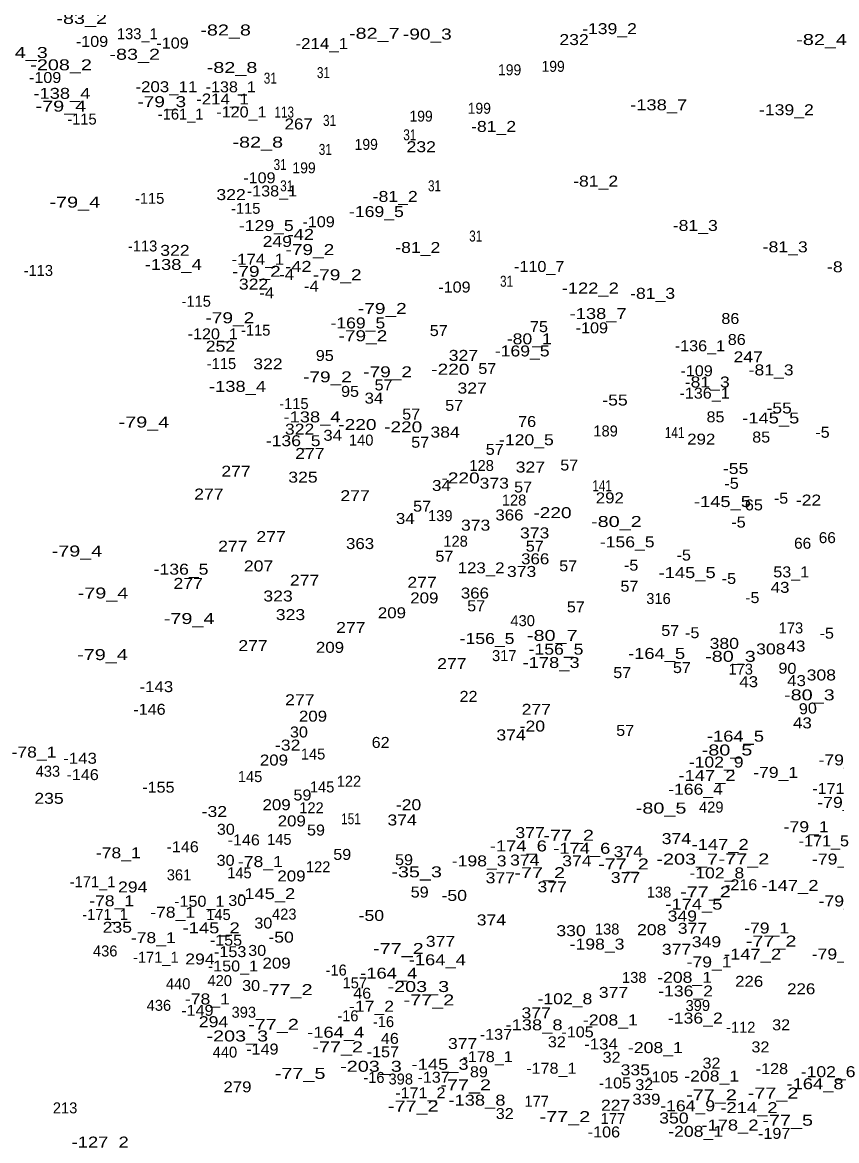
# Model space of a CAD drawing. Extents: x -658110 to -655750, y -1000429 to -997657.
# Drawn here: x -657300 to -657003, y -998729.8 to -998321.9 of the extents above; entities that cross this region are included whole.
import ezdxf
from ezdxf.enums import TextEntityAlignment as Align

# ---------------------------------------------------------------- set-up
doc = ezdxf.new("R2010")
doc.units = 0
doc.header["$LTSCALE"] = 1.6
doc.layers.add('24', color=7, linetype='Continuous')

msp = doc.modelspace()

# ---------------------------------------------------------------- texts
at = {"layer": '24'}
for s, width, p in [('-83_2', 1.35, (-657278.34, -998322.43)), ('-139_2', 1.2, (-657085.831, -998326.15)), ('-82_8', 1.35, (-657225.85, -998326.64)), ('-82_7', 1.35, (-657171.62, -998327.85)), ('-90_3', 1.3, (-657152.27, -998328.13)), ('232', 1.2, (-657098.76, -998330.13)), ('-82_4', 1.35, (-657008.49, -998330.12)), ('-109', 1.1, (-657274.58, -998330.81)), ('-109', 1.1, (-657245.21, -998331.39)), ('-214_1', 1.15, (-657190.77, -998331.59)), ('-84_3', 1.35, (-657299.94, -998334.85)), ('-83_2', 1.35, (-657259, -998335.49)), ('-208_2', 1.35, (-657285.86, -998339.34)), ('-82_8', 1.35, (-657223.52, -998340.31)), ('31', 0.8, (-657190.169, -998342.18)), ('199', 0.95, (-657122.26, -998341.15)), ('199', 0.95, (-657106.4, -998339.9)), ('-109', 1.1, (-657291.68, -998343.97)), ('31', 0.8, (-657209.559, -998344.21)), ('-138_4', 1.25, (-657285.559, -998349.75)), ('-203_11', 1.15, (-657247.45, -998347.33)), ('-138_1', 1.1, (-657223.98, -998347.38)), ('-79_4', 1.35, (-657285.931, -998354.42)), ('-79_3', 1.3, (-657249.15, -998352.78)), ('-214_1', 1.15, (-657227.01, -998351.81)), ('-138_7', 1.25, (-657067.9, -998353.93)), ('-120_1', 1.1, (-657220.08, -998356.53)), ('113', 0.8, (-657204.47, -998356.6)), ('199', 0.95, (-657154.56, -998358.07)), ('199', 0.95, (-657133.32, -998355.19)), ('-139_2', 1.2, (-657021.321, -998355.73)), ('267', 1.15, (-657199.19, -998360.91)), ('31', 0.8, (-657187.939, -998359.63)), ('-81_2', 1.2, (-657128.12, -998361.81)), ('31', 0.8, (-657158.669, -998364.87)), ('-82_8', 1.35, (-657214.12, -998367.56)), ('31', 0.8, (-657189.49, -998370.2)), ('199', 0.95, (-657174.56, -998368.36)), ('232', 1.2, (-657154.5, -998369.22)), ('31', 0.8, (-657205.97, -998375.72)), ('199', 0.95, (-657197.24, -998376.92)), ('-109', 1.1, (-657213.53, -998380.56)), ('31', 0.8, (-657203.559, -998383.49)), ('31', 0.8, (-657149.65, -998383.48)), ('-81_2', 1.2, (-657090.9, -998381.77)), ('322', 1.2, (-657223.85, -998386.69)), ('-138_1', 1.1, (-657208.949, -998385.37)), ('-81_2', 1.2, (-657164, -998387.36)), ('-79_4', 1.35, (-657280.851, -998389.44)), ('-169_5', 1.2, (-657170.84, -998392.88)), ('-129_5', 1.2, (-657211.02, -998397.98)), ('-109', 1.1, (-657191.93, -998396.6)), ('-81_3', 1.2, (-657054.559, -998397.95)), ('249', 1.2, (-657206.99, -998403.78)), ('-42', 1.25, (-657198.43, -998401.21)), ('31', 0.8, (-657134.63, -998401.81)), ('322', 1.2, (-657244.34, -998407.03)), ('-79_2', 1.3, (-657195.111, -998406.75)), ('-81_2', 1.2, (-657155.76, -998405.98)), ('-81_3', 1.2, (-657021.75, -998405.75)), ('-138_4', 1.25, (-657244.939, -998412.19)), ('-174_1', 1.15, (-657214.13, -998410.29)), ('-79_2', 1.3, (-657214.63, -998414.69)), ('-4', 1.15, (-657203.59, -998415.79)), ('-42', 1.25, (-657199.32, -998412.89)), ('-79_2', 1.3, (-657185.15, -998415.94)), ('-110_7', 1.1, (-657111.471, -998412.91)), ('-81_3', 1.2, (-656998.29, -998413.02)), ('322', 1.2, (-657215.65, -998419.33)), ('-4', 1.15, (-657194.58, -998420.06)), ('31', 0.8, (-657123.38, -998418.3)), ('-4', 1.15, (-657210.86, -998422.48)), ('-109', 1.1, (-657142.39, -998420.42)), ('-122_2', 1.25, (-657092.86, -998420.79)), ('-81_3', 1.2, (-657070.12, -998422.72)), ('-79_2', 1.3, (-657168.701, -998428.23)), ('-79_2', 1.3, (-657224.301, -998431.62)), ('-138_7', 1.25, (-657089.98, -998430.09)), ('86', 1.1, (-657041.76, -998431.9)), ('-169_5', 1.2, (-657177.62, -998433.52)), ('57', 1.1, (-657148.12, -998436.3)), ('75', 1.1, (-657111.56, -998434.86)), ('-109', 1.1, (-657092.27, -998435.3)), ('-120_1', 1.1, (-657230.54, -998437.49)), ('-79_2', 1.3, (-657175.77, -998438.19)), ('-80_1', 1.2, (-657115.09, -998439.31)), ('86', 1.1, (-657039.43, -998439.56)), ('252', 1.2, (-657227.73, -998441.98)), ('-169_5', 1.2, (-657117.67, -998443.73)), ('-136_1', 1.1, (-657052.861, -998441.84)), ('322', 1.2, (-657210.419, -998448.44)), ('95', 1.1, (-657189.68, -998445.39)), ('327', 1.2, (-657139.12, -998445.35)), ('247', 1.2, (-657035.25, -998445.89)), ('-79_2', 1.3, (-657166.77, -998451.35)), ('-220', 1.3, (-657143.89, -998450.4)), ('57', 1.1, (-657130.41, -998450.14)), ('-109', 1.1, (-657054.06, -998450.97)), ('-81_3', 1.2, (-657026.89, -998450.65)), ('-138_4', 1.25, (-657221.51, -998456.65)), ('-79_2', 1.3, (-657188.721, -998453.18)), ('57', 1.1, (-657168.24, -998456.13)), ('-81_3', 1.2, (-657050.189, -998455.06)), ('95', 1.1, (-657180.47, -998458.48)), ('34', 1.15, (-657171.75, -998460.94)), ('327', 1.2, (-657135.93, -998457.27)), ('-136_1', 1.1, (-657051.16, -998459.13)), ('57', 1.1, (-657142.5, -998463.58)), ('-55', 1.2, (-657083.83, -998461.65)), ('-55', 1.2, (-657023.96, -998464.54)), ('-138_4', 1.25, (-657194.34, -998467.79)), ('57', 1.1, (-657158.16, -998466.78)), ('85', 1.1, (-657047.179, -998467.78)), ('-145_5', 1.25, (-657027.03, -998468.19)), ('-79_4', 1.35, (-657255.64, -998469.67)), ('322', 1.2, (-657198.87, -998472.28)), ('-220', 1.3, (-657177.79, -998470.57)), ('-220', 1.3, (-657161.08, -998471.43)), ('384', 1.2, (-657145.799, -998473.34)), ('76', 1.1, (-657115.88, -998469.47)), ('-136_5', 1.2, (-657201.211, -998476.49)), ('34', 1.15, (-657186.799, -998474.5)), ('57', 1.1, (-657154.88, -998477.03)), ('-120_5', 1.2, (-657116.14, -998476.14)), ('141', 0.8, (-657062.079, -998473.52)), ('292', 1.15, (-657052.37, -998475.91)), ('85', 1.1, (-657030.51, -998475.15)), ('-5', 1.1, (-657008.16, -998473.4)), ('277', 1.2, (-657195.111, -998481.11)), ('57', 1.1, (-657127.7, -998479.64)), ('57', 1.1, (-657100.52, -998485.35)), ('277', 1.2, (-657222.051, -998487.6)), ('327', 1.2, (-657114.69, -998486.08)), ('-55', 1.2, (-657039.84, -998486.62)), ('325', 1.2, (-657197.64, -998489.77)), ('34', 1.15, (-657147.13, -998492.82)), ('-220', 1.3, (-657140.15, -998490.06)), ('373', 1.2, (-657127.87, -998491.98)), ('57', 1.1, (-657117.35, -998493.38)), ('141', 0.8, (-657088.54, -998492.91)), ('-5', 1.1, (-657041.31, -998492.02)), ('277', 1.2, (-657231.941, -998495.94)), ('277', 1.2, (-657178.63, -998496.53)), ('292', 1.15, (-657085.72, -998497.34)), ('-5', 1.1, (-657023.28, -998497.45)), ('57', 1.1, (-657154.19, -998500.35)), ('-145_5', 1.25, (-657044.65, -998498.68)), ('65', 1.1, (-657033.17, -998499.9)), ('-22', 1.2, (-657013.25, -998498.13)), ('34', 1.15, (-657160.319, -998504.86)), ('366', 1.15, (-657122.33, -998503.56)), ('-220', 1.3, (-657106.63, -998502.73)), ('-80_2', 1.35, (-657083.329, -998505.97)), ('373', 1.2, (-657134.66, -998507.3)), ('373', 1.2, (-657113.14, -998510.12)), ('-5', 1.1, (-657038.79, -998506.18)), ('277', 1.2, (-657209.26, -998511.46)), ('363', 1.15, (-657176.81, -998514.01)), ('-156_5', 1.2, (-657079.38, -998513.39)), ('66', 1.05, (-657015.39, -998513.89)), ('66', 1.05, (-657006.4, -998511.85)), ('-79_4', 1.35, (-657280.071, -998516.73)), ('277', 1.2, (-657223.221, -998514.95)), ('57', 1.1, (-657113.1, -998514.94)), ('-5', 1.1, (-657058.76, -998518.2)), ('207', 1.2, (-657213.82, -998522.18)), ('57', 1.1, (-657146.07, -998518.63)), ('366', 1.15, (-657112.93, -998519.56)), ('57', 1.1, (-657100.9, -998522.12)), ('-5', 1.1, (-657077.95, -998521.89)), ('-136_5', 1.2, (-657242.111, -998523.36)), ('123_2', 1.15, (-657132.67, -998522.86)), ('373', 1.2, (-657117.89, -998524.18)), ('-145_5', 1.25, (-657057.52, -998524.61)), ('53_1', 1.1, (-657019.55, -998524.35)), ('277', 1.2, (-657239.5, -998528.53)), ('277', 1.2, (-657197.041, -998527.36)), ('277', 1.2, (-657154.201, -998528.14)), ('57', 1.1, (-657078.57, -998529.56)), ('-5', 1.1, (-657042.28, -998526.74)), ('43', 1.15, (-657023.63, -998529.98)), ('-79_4', 1.35, (-657270.571, -998532.05)), ('323', 1.2, (-657206.73, -998533.14)), ('209', 1.15, (-657153.37, -998533.83)), ('366', 1.15, (-657134.93, -998532.06)), ('-5', 1.1, (-657033.75, -998533.72)), ('57', 1.1, (-657134.46, -998536.7)), ('57', 1.1, (-657098.12, -998537.11)), ('-79_4', 1.35, (-657239.16, -998541.36)), ('323', 1.2, (-657202.179, -998539.93)), ('209', 1.15, (-657165.191, -998539.26)), ('277', 1.2, (-657180.181, -998544.62)), ('57', 1.1, (-657063.68, -998545.71)), ('-5', 1.1, (-657055.66, -998546.52)), ('-5', 1.1, (-657006.61, -998546.71)), ('-156_5', 1.2, (-657130.49, -998548.64)), ('-80_7', 1.35, (-657106.71, -998547.53)), ('380', 1.2, (-657043.97, -998550.42)), ('-79_4', 1.35, (-657270.76, -998554.52)), ('277', 1.2, (-657215.851, -998551.22)), ('209', 1.15, (-657187.78, -998551.87)), ('-156_5', 1.2, (-657105.341, -998552.54)), ('-164_5', 1.25, (-657068.65, -998554.09)), ('308', 1.2, (-657027, -998552.44)), ('43', 1.15, (-657017.819, -998551.4)), ('277', 1.2, (-657143.341, -998557.81)), ('-178_3', 1.25, (-657107.13, -998557.41)), ('-80_3', 1.35, (-657041.72, -998555.15)), ('57', 1.1, (-657081.19, -998561.09)), ('57', 1.1, (-657059.43, -998559.25)), ('308', 1.2, (-657008.579, -998561.94)), ('-143', 1.15, (-657251.11, -998566.21)), ('43', 1.15, (-657035.069, -998564.4)), ('43', 1.15, (-657017.62, -998564.01)), ('277', 1.2, (-657198.78, -998570.99)), ('22', 1.1, (-657137.25, -998569.75)), ('-80_3', 1.35, (-657012.939, -998569.21)), ('-146', 1.1, (-657253.62, -998574.48)), ('277', 1.2, (-657112.52, -998574.48)), ('209', 1.15, (-657193.981, -998576.98)), ('43', 1.15, (-657015.48, -998579.43)), ('30', 1.1, (-657199.11, -998582.75)), ('-20', 1.2, (-657113.97, -998580.59)), ('57', 1.1, (-657080.12, -998582.18)), ('-32', 1.2, (-657203.21, -998587.53)), ('62', 1.1, (-657169.3, -998586.56)), ('374', 1.2, (-657121.73, -998583.82)), ('-164_5', 1.25, (-657039.9, -998584.28)), ('-78_1', 1.2, (-657295.75, -998590.08)), ('-80_5', 1.35, (-657042.98, -998589.31)), ('-143', 1.15, (-657278.95, -998592.34)), ('209', 1.15, (-657208.221, -998592.99)), ('-102_9', 1.2, (-657046.931, -998593.72)), ('-79_1', 1.2, (-657001.4, -998592.93)), ('-146', 1.1, (-657278, -998598.3)), ('-147_2', 1.25, (-657050.27, -998598.61)), ('-79_1', 1.2, (-657025.23, -998597.48)), ('-155', 1.1, (-657250.37, -998602.89)), ('-166_4', 1.2, (-657054.459, -998603.63)), ('-171_5', 1.1, (-657002.721, -998603.37)), ('235', 1.2, (-657290.26, -998606.95)), ('59', 1.1, (-657197.83, -998605.74)), ('-32', 1.2, (-657229.96, -998611.77)), ('209', 1.15, (-657207.25, -998609.28)), ('-20', 1.2, (-657159.14, -998609.29)), ('-80_5', 1.35, (-657067.02, -998610.52)), ('-79_1', 1.2, (-657001.83, -998608.42)), ('209', 1.15, (-657201.731, -998615.19)), ('151', 0.8, (-657180.13, -998614.41)), ('374', 1.2, (-657161.47, -998614.85)), ('30', 1.1, (-657225.77, -998618.24)), ('59', 1.1, (-657192.89, -998618.51)), ('377', 1.2, (-657114.801, -998619.46)), ('-79_1', 1.2, (-657014.11, -998617.31)), ('-146', 1.1, (-657219.24, -998622.12)), ('-174_6', 1.25, (-657119.081, -998624.32)), ('-77_2', 1.35, (-657100.74, -998620.44)), ('374', 1.2, (-657061.43, -998621.64)), ('-147_2', 1.25, (-657045.47, -998623.77)), ('-171_5', 1.1, (-657007.66, -998622.48)), ('-78_1', 1.2, (-657264.99, -998626.84)), ('-146', 1.1, (-657241.52, -998624.62)), ('59', 1.1, (-657183.31, -998627.41)), ('-174_6', 1.25, (-657095.941, -998625.18)), ('374', 1.2, (-657078.97, -998626.4)), ('30', 1.1, (-657225.86, -998629.58)), ('-78_1', 1.2, (-657213.17, -998630.03)), ('59', 1.1, (-657160.78, -998629.35)), ('-198_3', 1.2, (-657133.38, -998629.78)), ('374', 1.2, (-657116.74, -998629.47)), ('374', 1.2, (-657097.73, -998629.75)), ('-77_2', 1.35, (-657080.731, -998630.9)), ('-203_7', 1.35, (-657057.49, -998629.12)), ('-77_2', 1.35, (-657036.821, -998629.05)), ('-79_1', 1.2, (-657003.77, -998629.11)), ('209', 1.15, (-657201.831, -998635.27)), ('-35_3', 1.35, (-657156.179, -998633.78)), ('377', 1.2, (-657125.66, -998635.94)), ('-77_2', 1.35, (-657111.28, -998634.07)), ('377', 1.2, (-657080, -998635.85)), ('-102_8', 1.2, (-657046.699, -998634.16)), ('294', 1.2, (-657259.73, -998639.29)), ('377', 1.2, (-657106.75, -998639.24)), ('-216', 1.1, (-657037.83, -998638.48)), ('-147_2', 1.25, (-657020.03, -998638.74)), ('-78_1', 1.2, (-657267.41, -998644.35)), ('-150_1', 1.1, (-657235.46, -998644.51)), ('30', 1.1, (-657221.6, -998644.22)), ('-145_2', 1.25, (-657210.87, -998641.73)), ('59', 1.1, (-657155.07, -998641.15)), ('-50', 1.2, (-657142.46, -998642.38)), ('-77_2', 1.35, (-657050.821, -998641.08)), ('-79_1', 1.2, (-657001.35, -998644.4)), ('-78_1', 1.2, (-657245.17, -998648.51)), ('-174_5', 1.25, (-657055.06, -998645.56)), ('30', 1.1, (-657212.1, -998652.46)), ('-50', 1.2, (-657172.69, -998649.69)), ('374', 1.2, (-657128.9, -998651.31)), ('349', 1.2, (-657059.28, -998649.88)), ('235', 1.2, (-657265.35, -998653.98)), ('-145_2', 1.25, (-657231.12, -998654.21)), ('330', 1.2, (-657099.87, -998655.23)), ('208', 1.2, (-657070.449, -998654.88)), ('377', 1.2, (-657055.571, -998654.37)), ('-79_1', 1.2, (-657028.53, -998654.26)), ('-78_1', 1.2, (-657252.23, -998657.79)), ('-155', 1.1, (-657225.711, -998658.7)), ('-50', 1.2, (-657205.61, -998657.59)), ('377', 1.2, (-657147.471, -998659.12)), ('-198_3', 1.2, (-657090.38, -998660.13)), ('349', 1.2, (-657050.47, -998659.28)), ('-77_2', 1.35, (-657026.87, -998659.03)), ('-153', 1.1, (-657224.181, -998662.89)), ('30', 1.1, (-657214.329, -998662.45)), ('-77_2', 1.35, (-657162.831, -998661.75)), ('377', 1.2, (-657061.39, -998662.03)), ('-147_2', 1.25, (-657033.66, -998663.8)), ('-79_1', 1.2, (-657003.87, -998663.75)), ('294', 1.2, (-657235.21, -998665.57)), ('-150_1', 1.1, (-657223.17, -998668.13)), ('209', 1.15, (-657207.26, -998667.08)), ('-164_4', 1.25, (-657148.64, -998665.86)), ('-79_1', 1.2, (-657049.51, -998666.64)), ('-164_4', 1.25, (-657166.35, -998670.74)), ('-208_1', 1.2, (-657058.449, -998672.26)), ('30', 1.1, (-657216.559, -998675.25)), ('-77_2', 1.35, (-657203.351, -998676.74)), ('-203_3', 1.35, (-657155.569, -998675.62)), ('-136_2', 1.2, (-657058.081, -998677.24)), ('226', 1.15, (-657034.9, -998673.72)), ('226', 1.15, (-657015.91, -998676.44)), ('-78_1', 1.2, (-657232.5, -998680.15)), ('46', 1.1, (-657176.03, -998678.05)), ('-77_2', 1.35, (-657151.711, -998680.51)), ('-102_8', 1.2, (-657102.1, -998680.07)), ('377', 1.2, (-657084.37, -998677.75)), ('-149', 1.1, (-657236.15, -998684.3)), ('-17_2', 1.2, (-657172.63, -998682.8)), ('377', 1.2, (-657112.571, -998685.21)), ('294', 1.2, (-657230.26, -998688.45)), ('-77_2', 1.35, (-657208.38, -998689.41)), ('-138_8', 1.25, (-657113.36, -998689.6)), ('-208_1', 1.2, (-657085.52, -998687.81)), ('-136_2', 1.2, (-657054.53, -998687.13)), ('32', 1.1, (-657023.23, -998689.59)), ('-203_3', 1.35, (-657221.59, -998693.65)), ('-164_4', 1.25, (-657185.7, -998692.3)), ('-137', 1.1, (-657127.25, -998693.05)), ('-105', 1.1, (-657097.49, -998692.17)), ('-77_2', 1.35, (-657184.99, -998697.64)), ('46', 1.1, (-657165.95, -998694.54)), ('377', 1.2, (-657139.41, -998696.41)), ('32', 1.1, (-657105.049, -998695.8)), ('-134', 1.15, (-657088.94, -998696.57)), ('32', 1.1, (-657030.799, -998697.64)), ('-149', 1.1, (-657212.441, -998698.42)), ('-157', 1.1, (-657168.5, -998699.43)), ('-178_1', 1.1, (-657130.291, -998701.2)), ('32', 1.1, (-657085.079, -998701.42)), ('-208_1', 1.2, (-657069.1, -998697.9)), ('-203_3', 1.35, (-657172.829, -998704.71)), ('-145_3', 1.25, (-657147.63, -998703.98)), ('-178_1', 1.1, (-657107.051, -998705.42)), ('32', 1.1, (-657048.63, -998703.55)), ('-128', 1.1, (-657026.611, -998705.58)), ('-77_5', 1.35, (-657198.66, -998707.31)), ('-137', 1.1, (-657149.99, -998708.71)), ('89', 1.1, (-657133.47, -998706.72)), ('335', 1.2, (-657076.429, -998706.01)), ('-105', 1.1, (-657066.571, -998708.6)), ('-208_1', 1.2, (-657048.559, -998708.27)), ('-102_6', 1.2, (-657006.101, -998706.69)), ('279', 1.15, (-657221.54, -998712.21)), ('-77_2', 1.35, (-657138.301, -998711.49)), ('-105', 1.1, (-657083.851, -998710.8)), ('32', 1.1, (-657073.15, -998711.41)), ('-164_8', 1.25, (-657010.86, -998711.08)), ('-171_2', 1.1, (-657154.821, -998714.4)), ('-138_8', 1.25, (-657134.189, -998717.07)), ('339', 1.15, (-657072.39, -998716.71)), ('-77_2', 1.35, (-657048.63, -998715.14)), ('-77_2', 1.35, (-657026.191, -998714.49)), ('-77_2', 1.35, (-657157.41, -998719.22)), ('32', 1.1, (-657124.049, -998721.96)), ('227', 1.2, (-657083.6, -998718.93)), ('-164_9', 1.2, (-657057.329, -998719.12)), ('-214_2', 1.25, (-657034.97, -998719.8)), ('-77_2', 1.35, (-657102.111, -998723.08)), ('350', 1.2, (-657062.35, -998723.59)), ('-178_2', 1.25, (-657041.92, -998726.15)), ('-77_5', 1.35, (-657020.851, -998724.39)), ('-106', 1.1, (-657087.87, -998728.67)), ('-208_1', 1.2, (-657054.41, -998728.44)), ('-197', 1.1, (-657025.77, -998729.19)), ('-127_2', 1.25, (-657271.59, -998732.37))]:
    msp.add_text(s, height=4, dxfattribs=dict(at, width=width)).set_placement(p, align=Align.CENTER)
for s, p in [('133_1', (-657258.05, -998328)), ('-115', (-657278.24, -998359.14)), ('-161_1', (-657242.24, -998357.31)), ('-115', (-657253.561, -998388.05)), ('-115', (-657218.52, -998391.7)), ('-113', (-657256.13, -998405.44)), ('-113', (-657294.15, -998414.37)), ('-115', (-657236.571, -998425.59)), ('-115', (-657214.87, -998436.15)), ('-115', (-657227.351, -998448.35)), ('-115', (-657200.941, -998462.94)), ('189', (-657087.26, -998472.93)), ('140', (-657176.4, -998476.26)), ('128', (-657132.47, -998485.53)), ('128', (-657120.65, -998498.13)), ('139', (-657147.551, -998503.82)), ('128', (-657141.97, -998513.16)), ('316', (-657067.951, -998534.06)), ('430', (-657117.505, -998542.13)), ('173', (-657019.66, -998544.78)), ('317', (-657124.221, -998554.89)), ('173', (-657037.981, -998559.81)), ('145', (-657193.959, -998590.79)), ('433', (-657290.671, -998597.08)), ('145', (-657216.929, -998599.03)), ('145', (-657190.66, -998602.81)), ('122', (-657180.86, -998600.72)), ('122', (-657194.53, -998610.41)), ('429', (-657048.717, -998610.15)), ('145', (-657206.27, -998621.92)), ('122', (-657192.1, -998631.94)), ('361', (-657242.841, -998634.88)), ('145', (-657220.809, -998634.13)), ('-171_1', (-657274.37, -998637.39)), ('138', (-657067.78, -998641.17)), ('-171_1', (-657269.811, -998649.32)), ('145', (-657228.459, -998649.36)), ('423', (-657204.461, -998649.19)), ('138', (-657086.689, -998654.64)), ('436', (-657269.757, -998662.64)), ('-171_1', (-657251.301, -998664.93)), ('-16', (-657185.52, -998669.61)), ('138', (-657076.799, -998672.29)), ('440', (-657243.16, -998674.6)), ('420', (-657227.995, -998673.45)), ('157', (-657178.74, -998674.27)), ('436', (-657250.177, -998682.47)), ('393', (-657219.213, -998684.99)), ('399', (-657053.628, -998682.53)), ('-16', (-657181.26, -998686.29)), ('-16', (-657168.26, -998688.43)), ('-112', (-657037.971, -998690.48)), ('440', (-657226.1, -998699.54)), ('-16', (-657171.76, -998708.78)), ('398', (-657161.973, -998709.35)), ('177', (-657112.4, -998717.47)), ('213', (-657284.4, -998719.89)), ('177', (-657084.58, -998723.76))]:
    msp.add_text(s, height=4, dxfattribs=at).set_placement(p, align=Align.CENTER)
at = {"layer": '24', "width": 1.1}
for rotation, p in [(358.716, (-657020.991, -998559.52)), (4.126, (-657013.333, -998574.144))]:
    msp.add_text('90', height=4, rotation=rotation, dxfattribs=at).set_placement(p, align=Align.CENTER)

doc.saveas('drawing.dxf')
